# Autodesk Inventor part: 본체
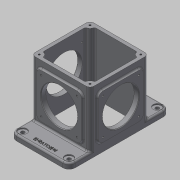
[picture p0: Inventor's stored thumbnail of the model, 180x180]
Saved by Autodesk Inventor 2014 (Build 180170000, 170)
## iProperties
Created: 2018-09
Part Number: 본체
Material: 일반
Document SubType Name: Modeling
Designer: mduedu
Density: 1 g/cm^3
Appearance: 기본값
Mass: 324.716 g
Surface Area: 940.033 cm^2
Volume: 324.716 cm^3
Author: mduedu
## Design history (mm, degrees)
sketch "스케치1"
  geometry: L1 (90, 52.5)-(-90, 52.5); L2 (-90, 52.5)-(-90, -52.5); L3 (-90, -52.5)-(90, -52.5); L4 (90, -52.5)-(90, 52.5); L5 (90, 52.5)-(-90, -52.5); L6 (-90, 52.5)-(90, -52.5); 1 further point
  constraints: 12 end point, 2 midpoint, 2 parallel, 1 horizontal, 1 perpendicular
  dimensions: "d0" = 180 distance of L3.end L2.end; "d1" = 105 distance of L2.end L1.end
extrude "돌출1" new body sketch "스케치1" distance "d2" = 10; taper "d3" = 0 deg
sketch "스케치2"
  geometry: L1 (-52.5, -52.5)-(52.5, -52.5); L2 (52.5, -52.5)-(52.5, 52.5); L3 (52.5, 52.5)-(-52.5, 52.5); L4 (-52.5, 52.5)-(-52.5, -52.5); L5 (-52.5, -52.5)-(52.5, 52.5); L6 (52.5, -52.5)-(-52.5, 52.5); 1 further point
  constraints: 12 end point, 2 midpoint, 2 parallel, 1 horizontal, 1 perpendicular
  dimensions: "d4" = 105 distance of L3.end L2.end; "d5" = 105 distance of L2.end L1.end
extrude "돌출2" join sketch "스케치2" distance "d6" = 100; taper "d7" = 0 deg
sketch "스케치14"
  geometry: L1 (-52.5, 52.5)-(52.5, 52.5) reference; L2 (52.5, 52.5)-(52.5, -52.5) reference; L3 (52.5, -52.5)-(-52.5, -52.5) reference; L4 (-52.5, -52.5)-(-52.5, 52.5) reference; L5 (46.5, 46.5)-(-46.5, 46.5); L6 (-46.5, 46.5)-(-46.5, -46.5); L7 (-46.5, -46.5)-(46.5, -46.5); L8 (46.5, -46.5)-(46.5, 46.5); 1 further point
  constraints: 8 end point, 3 other
  dimensions: "d85" = 6 distance between parallel lines of L5 L1
extrude "돌출10" cut sketch "스케치14" stored distance "d86" = 10; taper "d87" = 0 deg
fillet "모깎기1" dims "d12" = 7
sketch "스케치15"
  geometry: A1 r 7 centre (-45.5, 45.5) between (-45.5, 52.5) and (-52.5, 45.5) reference; A2 r 7 centre (45.5, 45.5) between (52.5, 45.5) and (45.5, 52.5) reference; A3 r 7 centre (45.5, -45.5) between (45.5, -52.5) and (52.5, -45.5) reference; A4 r 7 centre (-45.5, -45.5) between (-52.5, -45.5) and (-45.5, -52.5) reference; 5 further points
  constraints: 4 coincident, 4 vertical alignment, 8 other
extrude "돌출11" join sketch "스케치15" stored distance "d88" = 10; taper "d89" = 0 deg
fillet "모깎기15" dims "d90" = 3
sketch "스케치6"
  geometry: L1 (50, 17.5)-(130, 17.5); L2 (130, 17.5)-(130, 97.5); L3 (130, 97.5)-(50, 97.5); L4 (50, 97.5)-(50, 17.5); L5 (50, 17.5)-(130, 97.5); L6 (130, 17.5)-(50, 97.5); L7 (0, 0)-(180, 0) reference; 4 further points
  constraints: 12 end point, 4 midpoint, 2 parallel, 1 horizontal, 1 perpendicular, 1 vertical alignment
  dimensions: "d25" = 80 distance of L3.end L2.end; "d26" = 80 distance of L2.end L1.end; "d27" = 57.5 distance of point (90, 0) point (90, 57.5)
extrude "돌출6" join sketch "스케치6" distance "d28" = 3; taper "d29" = 0 deg
fillet "모깎기7" dims "d30" = 8
sketch "스케치7"
  geometry: C1 r 32.5 at (90, 57.5); 1 further point
  constraints: 1 centre point, 1 vertical alignment
  dimensions: "d32" = 65 diameter of C1; "d33" = 57.5 distance of C1.centre point (90, 0)
extrude "돌출7" cut sketch "스케치7" stored distance "d34" = 3; taper "d35" = 0 deg
fillet "모깎기9" dims "d36" = 3
sketch "스케치8"
  geometry: L1 (5.5, 7.5)-(85.5, 7.5); L2 (85.5, 7.5)-(85.5, 87.5); L3 (85.5, 87.5)-(5.5, 87.5); L4 (5.5, 87.5)-(5.5, 7.5); L5 (5.5, 7.5)-(85.5, 87.5); L6 (85.5, 7.5)-(5.5, 87.5); L7 (-7, -10)-(98, -10) reference; C1 r 32.5 at (45.5, 47.5); 4 further points
  constraints: 12 end point, 4 midpoint, 2 parallel, 1 centre point, 1 coincident, 1 horizontal, 1 perpendicular, 1 vertical alignment
  dimensions: "d37" = 80 distance of L3.end L2.end; "d38" = 80 distance of L2.end L1.end; "d39" = 57.5 distance from line of point (45.5, 47.5) L7; "d40" = 65 diameter of C1
extrude "돌출8" join sketch "스케치8" distance "d41" = 3; taper "d42" = 0 deg
fillet "모깎기10" dims "d43" = 8
extrude "돌출9" cut sketch "스케치8" stored distance "d44" = 3; taper "d45" = 0 deg
fillet "모깎기11" dims "d46" = 3
sketch "스케치9"
  geometry: L1 (50, 89.5)-(50, 25.5) reference; L2 (58, 17.5)-(122, 17.5) reference; L3 (130, 25.5)-(130, 89.5) reference; L4 (122, 97.5)-(58, 97.5) reference; C1 r 32.5 at (90, 57.5) reference; A1 r 8 centre (58, 89.5) between (58, 97.5) and (50, 89.5) reference; A2 r 8 centre (58, 25.5) between (50, 25.5) and (58, 17.5) reference; A3 r 8 centre (122, 25.5) between (122, 17.5) and (130, 25.5) reference; A4 r 8 centre (122, 89.5) between (130, 89.5) and (122, 97.5) reference; 5 further points
  constraints: 4 coincident
hole "구멍1" sketch "스케치9" at (58, 89.5), (122, 89.5), (122, 25.5), (58, 25.5) diameter "d47" = 3.242; stored, may be unused: countersink angle "d51" = 90 deg, drill point angle "d53" = 118 deg; dims "d48" = 6, "d49" = 4, "d50" = 2, "d52" = 9
sketch "스케치10" dims "d30" = 8
  geometry: L1 (13.5, 7.5)-(77.5, 7.5) reference; L2 (85.5, 15.5)-(85.5, 79.5) reference; L3 (77.5, 87.5)-(13.5, 87.5) reference; L4 (5.5, 79.5)-(5.5, 15.5) reference; C1 r 32.5 at (45.5, 47.5) reference; A1 r 8 centre (13.5, 15.5) between (5.5, 15.5) and (13.5, 7.5) reference; A2 r 8 centre (77.5, 15.5) between (77.5, 7.5) and (85.5, 15.5) reference; A3 r 8 centre (77.5, 79.5) between (85.5, 79.5) and (77.5, 87.5) reference; A4 r 8 centre (13.5, 79.5) between (13.5, 87.5) and (5.5, 79.5) reference; 5 further points
  constraints: 4 coincident
hole "구멍2" sketch "스케치10" at (13.5, 79.5), (77.5, 79.5), (77.5, 15.5), (13.5, 15.5) diameter "d54" = 3.242; stored, may be unused: countersink angle "d58" = 90 deg, drill point angle "d60" = 118 deg; dims "d30" = 8, "d55" = 6, "d56" = 4, "d57" = 2, "d59" = 9
fillet "모깎기12" dims "d68" = 11
sketch "스케치16"
  geometry: A1 r 11 centre (-79, 41.5) between (-79, 52.5) and (-90, 41.5) reference; A2 r 11 centre (-79, -41.5) between (-90, -41.5) and (-79, -52.5) reference; A3 r 11 centre (79, 41.5) between (90, 41.5) and (79, 52.5) reference; A4 r 11 centre (79, -41.5) between (79, -52.5) and (90, -41.5) reference; 5 further points
  constraints: 4 coincident
hole "구멍5" sketch "스케치16" at (-79, 41.5), (79, 41.5), (79, -41.5), (-79, -41.5) diameter "d91" = 6.6; stored, may be unused: countersink angle "d95" = 90 deg, drill point angle "d97" = 118 deg; dims "d92" = 6, "d93" = 15, "d94" = 2, "d96" = 8
fillet "모깎기13" dims "d77" = 3
fillet "모깎기14" dims "d78" = 3
chamfer "모따기1" distance "d79" = 1; stored, may be unused: second distance "d80" = 2, angle "d81" = 45 deg
sketch "스케치17"
  geometry: A1 r 7 centre (-45.5, 45.5) between (-45.5, 52.5) and (-52.5, 45.5) reference; A2 r 7 centre (-45.5, -45.5) between (-52.5, -45.5) and (-45.5, -52.5) reference; A3 r 7 centre (45.5, -45.5) between (45.5, -52.5) and (52.5, -45.5) reference; A4 r 7 centre (45.5, 45.5) between (52.5, 45.5) and (45.5, 52.5) reference; 5 further points
  constraints: 4 coincident
hole "구멍6" sketch "스케치17" at (-45.5, 45.5), (45.5, 45.5), (45.5, -45.5), (-45.5, -45.5) diameter "d98" = 3.242; stored, may be unused: countersink angle "d102" = 90 deg, drill point angle "d104" = 118 deg; dims "d99" = 8, "d100" = 15, "d101" = 2, "d103" = 10
sketch "스케치13"
  geometry: L1 (90, -41.5)-(90, 41.5) reference; 2 further points
  constraints: 1 horizontal alignment, 1 other
  dimensions: "d82" = 10 distance from line of point (80, 0) L1
feature "엠보싱1" sketch "스케치13" dims "d0" = 180, "d1" = 105, "d25" = 80, "d26" = 80, "d27" = 57.5, "d83" = 0.5, "d84" = 0
node "솔리드1"
mirror "대칭1"
mirror "대칭2"
node "투영된 루프2"
node "투영된 루프3"
node "투영된 루프6"
